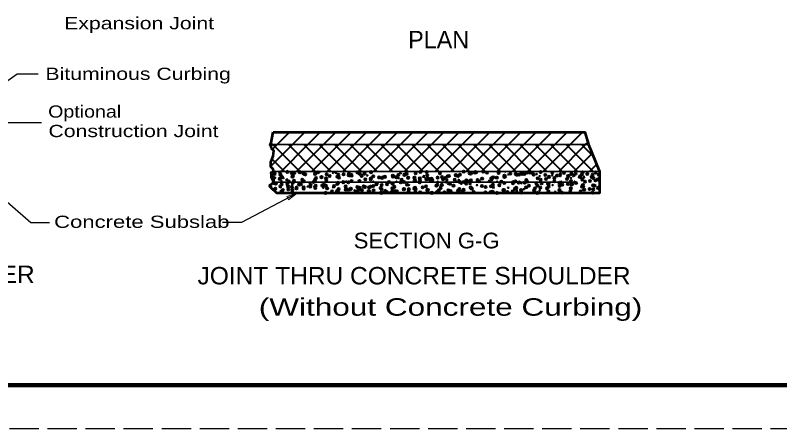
# Model space of a CAD drawing. Extents: x 14 to 49.3, y 28 to 50.
# Drawn here: x 22.75 to 31.51, y 28.04 to 32.78 of the extents above; entities that cross this region are included whole.
import ezdxf

# ---------------------------------------------------------------- set-up
doc = ezdxf.new("R2010")
doc.units = 0
doc.header["$LTSCALE"] = 0.056
doc.header["$PDMODE"] = 32
doc.header["$PDSIZE"] = 0.028
doc.linetypes.add('LONG_DASHED', pattern=[7.5, 6, -1.5])
doc.layers.add('1', color=7, linetype='Continuous', lineweight=35)
doc.layers.add('3', color=7, linetype='Continuous', lineweight=13)

msp = doc.modelspace()

# ---------------------------------------------------------------- hatches: boundary and pattern name
at = {"layer": '3'}
msp.add_hatch(color=256, dxfattribs=at).paths.add_polyline_path([(25.857, 30.706), (25.87625, 30.66908), (25.97725, 30.74567), (25.97725, 30.74567)])

# ---------------------------------------------------------------- linework, layer by layer
at = {"layer": '1', "lineweight": 53}
for p, q in [((25.67508, 31.301), (25.70025, 31.442)), ((29.31292, 31.301), (29.43892, 30.99242)), ((25.6835, 30.97483), (25.73383, 30.99242)), ((25.70767, 30.90667), (25.73192, 30.932)), ((25.70767, 30.86225), (25.70767, 30.90667)), ((25.73192, 30.84317), (25.70767, 30.86225))]:
    msp.add_line(p, q, dxfattribs=at)
at = {"layer": '1', "lineweight": 40}
for p, q in [((25.698, 31.42942), (25.71058, 31.442)), ((25.74633, 31.301), (25.88742, 31.442)), ((25.92317, 31.301), (26.06417, 31.442)), ((26.09992, 31.301), (26.24092, 31.442)), ((26.27667, 31.301), (26.41775, 31.442)), ((26.4535, 31.301), (26.5945, 31.442)), ((26.63025, 31.301), (26.77125, 31.442)), ((26.807, 31.301), (26.94808, 31.442)), ((26.98375, 31.301), (27.12483, 31.442)), ((27.16058, 31.301), (27.30158, 31.442)), ((27.33733, 31.301), (27.47842, 31.442)), ((27.51408, 31.301), (27.65517, 31.442)), ((27.69092, 31.301), (27.83192, 31.442)), ((27.86767, 31.301), (28.00875, 31.442)), ((28.04442, 31.301), (28.1855, 31.442)), ((28.22125, 31.301), (28.36225, 31.442)), ((28.398, 31.301), (28.53908, 31.442)), ((28.57475, 31.301), (28.71583, 31.442)), ((28.75158, 31.301), (28.89258, 31.442)), ((28.92833, 31.301), (29.06942, 31.442)), ((29.10508, 31.301), (29.24617, 31.442)), ((25.67508, 31.05292), (25.92317, 31.301)), ((25.69267, 31.24725), (25.74633, 31.301)), ((26.00733, 30.99242), (25.69883, 31.301)), ((25.79142, 30.99242), (26.09992, 31.301)), ((26.18417, 30.99242), (25.87558, 31.301)), ((25.96817, 30.99242), (26.27667, 31.301)), ((26.36092, 30.99242), (26.05242, 31.301)), ((26.14492, 30.99242), (26.4535, 31.301)), ((26.53767, 30.99242), (26.22917, 31.301)), ((26.32175, 30.99242), (26.63025, 31.301)), ((26.7145, 30.99242), (26.40592, 31.301)), ((26.4985, 30.99242), (26.807, 31.301)), ((26.89125, 30.99242), (26.58275, 31.301)), ((26.67525, 30.99242), (26.98375, 31.301)), ((27.068, 30.99242), (26.7595, 31.301)), ((26.852, 30.99242), (27.16058, 31.301)), ((27.24483, 30.99242), (26.93625, 31.301)), ((27.02883, 30.99242), (27.33733, 31.301)), ((27.42158, 30.99242), (27.11308, 31.301)), ((27.20558, 30.99242), (27.51408, 31.301)), ((27.59833, 30.99242), (27.28983, 31.301)), ((27.38233, 30.99242), (27.69092, 31.301)), ((27.77508, 30.99242), (27.46658, 31.301)), ((27.55917, 30.99242), (27.86767, 31.301)), ((27.95192, 30.99242), (27.64333, 31.301)), ((27.73592, 30.99242), (28.04442, 31.301)), ((28.12867, 30.99242), (27.82017, 31.301)), ((27.91267, 30.99242), (28.22125, 31.301)), ((28.30542, 30.99242), (27.99692, 31.301)), ((28.0895, 30.99242), (28.398, 31.301)), ((28.48225, 30.99242), (28.17367, 31.301)), ((28.26625, 30.99242), (28.57475, 31.301)), ((28.659, 30.99242), (28.3505, 31.301)), ((28.443, 30.99242), (28.75158, 31.301)), ((28.83575, 30.99242), (28.52725, 31.301)), ((28.61983, 30.99242), (28.92833, 31.301)), ((29.01258, 30.99242), (28.704, 31.301)), ((28.79658, 30.99242), (29.10508, 31.301)), ((29.18933, 30.99242), (28.88083, 31.301)), ((28.97333, 30.99242), (29.28192, 31.301)), ((29.36608, 30.99242), (29.05758, 31.301)), ((29.36708, 31.16825), (29.23433, 31.301)), ((29.28192, 31.301), (29.30575, 31.32483)), ((29.15017, 30.99242), (29.35517, 31.1975)), ((25.83058, 30.99242), (25.68817, 31.13483)), ((29.32692, 30.99242), (29.40642, 31.07192))]:
    msp.add_line(p, q, dxfattribs=at)
at = {"layer": '1'}
for p, q in [((25.67508, 31.301), (29.31292, 31.301)), ((25.73383, 30.99242), (29.43892, 30.99242)), ((25.80908, 30.91667), (25.82658, 30.92333)), ((25.82158, 30.90825), (25.82658, 30.92333)), ((26.02633, 30.99242), (26.03158, 30.98892)), ((26.03158, 30.98892), (26.03283, 30.99242)), ((26.23375, 30.99008), (26.23575, 30.99242)), ((26.23375, 30.99008), (26.24867, 30.98875)), ((26.24867, 30.98875), (26.248, 30.99242)), ((26.37842, 30.97725), (26.396, 30.984)), ((26.37842, 30.97725), (26.39092, 30.96883)), ((26.39092, 30.96883), (26.396, 30.984)), ((26.41308, 30.97433), (26.42508, 30.98875)), ((26.41308, 30.97433), (26.428, 30.97308)), ((26.428, 30.97308), (26.42508, 30.98875)), ((26.59233, 30.95867), (26.60442, 30.973)), ((26.59233, 30.95867), (26.60733, 30.95733)), ((26.60733, 30.95733), (26.60442, 30.973)), ((26.73775, 30.95725), (26.75525, 30.96392)), ((26.73775, 30.95725), (26.75017, 30.94883)), ((26.75017, 30.94883), (26.75525, 30.96392)), ((26.77167, 30.943), (26.78375, 30.95733)), ((26.77167, 30.943), (26.78658, 30.94167)), ((26.78667, 30.94167), (26.78375, 30.95733)), ((26.951, 30.92733), (26.96308, 30.94167)), ((26.951, 30.92733), (26.96592, 30.926)), ((26.96592, 30.926), (26.96308, 30.94167)), ((27.097, 30.93725), (27.1145, 30.94392)), ((27.097, 30.93725), (27.10942, 30.92883)), ((27.1095, 30.92883), (27.1145, 30.94392)), ((27.13033, 30.91158), (27.14233, 30.926)), ((27.14525, 30.91033), (27.14233, 30.926)), ((27.14458, 30.96958), (27.164, 30.98983)), ((27.14458, 30.96958), (27.16683, 30.96608)), ((27.16683, 30.96608), (27.164, 30.98983)), ((27.41133, 30.92817), (27.43083, 30.9485)), ((27.41133, 30.92817), (27.43358, 30.92475)), ((27.43358, 30.92475), (27.43083, 30.9485)), ((27.45633, 30.91717), (27.47383, 30.92392)), ((27.45633, 30.91717), (27.46875, 30.90883)), ((27.46875, 30.90883), (27.47383, 30.92392)), ((27.67433, 30.99242), (27.67883, 30.98942)), ((27.67883, 30.98942), (27.67983, 30.99242)), ((28.02567, 30.97783), (28.04317, 30.9845)), ((28.02567, 30.97783), (28.03808, 30.96942)), ((28.03808, 30.96942), (28.04317, 30.9845)), ((28.35083, 30.98983), (28.353, 30.99242)), ((28.35083, 30.98983), (28.36575, 30.9885)), ((28.36575, 30.9885), (28.36508, 30.99242)), ((28.38492, 30.95775), (28.40242, 30.9645)), ((28.38492, 30.95775), (28.39733, 30.94942)), ((28.39733, 30.94942), (28.40242, 30.9645)), ((28.53017, 30.97417), (28.54217, 30.9885)), ((28.53017, 30.97417), (28.54508, 30.97283)), ((28.54508, 30.97283), (28.54217, 30.9885)), ((28.7095, 30.9585), (28.7215, 30.97283)), ((28.7095, 30.9585), (28.72442, 30.95717)), ((28.72442, 30.95717), (28.7215, 30.97283)), ((28.72442, 30.95717), (28.7215, 30.97283)), ((28.74417, 30.93775), (28.76175, 30.9445)), ((28.74417, 30.93775), (28.75667, 30.92933)), ((28.75667, 30.92933), (28.76175, 30.9445)), ((28.88875, 30.94275), (28.90083, 30.95717)), ((28.88875, 30.94275), (28.90375, 30.9415)), ((28.90375, 30.9415), (28.90083, 30.95717)), ((28.97908, 30.96483), (28.99858, 30.98508)), ((28.97908, 30.96483), (29.00133, 30.96133)), ((29.00133, 30.96133), (28.99858, 30.98508)), ((29.06808, 30.92708), (29.08017, 30.94142)), ((29.06808, 30.92708), (29.083, 30.92575)), ((29.083, 30.92575), (29.08017, 30.94142)), ((29.1035, 30.91775), (29.121, 30.92442)), ((29.1035, 30.91775), (29.11592, 30.90933)), ((29.11592, 30.90933), (29.121, 30.92442)), ((29.24592, 30.92342), (29.26533, 30.94375)), ((29.24592, 30.92342), (29.26817, 30.92)), ((29.24742, 30.91142), (29.25942, 30.92575)), ((29.26233, 30.91008), (29.2595, 30.92575)), ((29.26817, 30.92), (29.26542, 30.94375)), ((29.32233, 30.99242), (29.326, 30.99)), ((29.326, 30.99), (29.32683, 30.99242)), ((25.70767, 30.87108), (29.15475, 30.87108)), ((25.7305, 30.84908), (25.7425, 30.86342)), ((25.7305, 30.84908), (25.74542, 30.84775)), ((25.74542, 30.84775), (25.7425, 30.86342)), ((25.80908, 30.91667), (25.82158, 30.90825)), ((25.84367, 30.89158), (25.86317, 30.91183)), ((25.84367, 30.89158), (25.86592, 30.88808)), ((25.86592, 30.88808), (25.86317, 30.91183)), ((25.90983, 30.83342), (25.92183, 30.84775)), ((25.90983, 30.83342), (25.92475, 30.83208)), ((25.92475, 30.83208), (25.92183, 30.84775)), ((26.08908, 30.81767), (26.10117, 30.83208)), ((26.10408, 30.81633), (26.10117, 30.83208)), ((26.1105, 30.85017), (26.12992, 30.8705)), ((26.1105, 30.85017), (26.13267, 30.84675)), ((26.13267, 30.84675), (26.12992, 30.8705)), ((26.16842, 30.89667), (26.18592, 30.90333)), ((26.16842, 30.89667), (26.18083, 30.88825)), ((26.18083, 30.88825), (26.18592, 30.90333)), ((26.52767, 30.87658), (26.54517, 30.88333)), ((26.52767, 30.87658), (26.54008, 30.86825)), ((26.54008, 30.86817), (26.54517, 30.88333)), ((26.887, 30.85658), (26.9045, 30.86333)), ((26.887, 30.85658), (26.89942, 30.84817)), ((26.89942, 30.84817), (26.9045, 30.86333)), ((27.13033, 30.91158), (27.14525, 30.91033)), ((27.24625, 30.83658), (27.26375, 30.84325)), ((27.24625, 30.83658), (27.25867, 30.82817)), ((27.25867, 30.82817), (27.26375, 30.84325)), ((27.30967, 30.89592), (27.32167, 30.91025)), ((27.30967, 30.89592), (27.32458, 30.89458)), ((27.32458, 30.89458), (27.32167, 30.91025)), ((27.48892, 30.88025), (27.501, 30.89458)), ((27.48892, 30.88025), (27.50392, 30.87892)), ((27.50392, 30.87892), (27.501, 30.89458)), ((27.66825, 30.86458), (27.68033, 30.87892)), ((27.66825, 30.86458), (27.68317, 30.86325)), ((27.67817, 30.88683), (27.69767, 30.90708)), ((27.67817, 30.88683), (27.70042, 30.88333)), ((27.68317, 30.86325), (27.68033, 30.87892)), ((27.70042, 30.88333), (27.69767, 30.90708)), ((27.81558, 30.89717), (27.83308, 30.90392)), ((27.81558, 30.89717), (27.828, 30.88875)), ((27.828, 30.88875), (27.83308, 30.90392)), ((27.84758, 30.84883), (27.85958, 30.86325)), ((27.84758, 30.84883), (27.8625, 30.84758)), ((27.8625, 30.8475), (27.85967, 30.86325)), ((27.945, 30.84542), (27.9645, 30.86575)), ((27.945, 30.84542), (27.96725, 30.842)), ((27.96725, 30.842), (27.9645, 30.86575)), ((28.02692, 30.83317), (28.03892, 30.8475)), ((28.02692, 30.83317), (28.04183, 30.83183)), ((28.04183, 30.83183), (28.03892, 30.8475)), ((28.17483, 30.87717), (28.19233, 30.88383)), ((28.17483, 30.87717), (28.18733, 30.86875)), ((28.18733, 30.86875), (28.19233, 30.88383)), ((28.20617, 30.8175), (28.21825, 30.83183)), ((28.22117, 30.81617), (28.21825, 30.83183)), ((28.53417, 30.85717), (28.55167, 30.86383)), ((28.53417, 30.85717), (28.54658, 30.84875)), ((28.54658, 30.84875), (28.55167, 30.86383)), ((28.89342, 30.83708), (28.91092, 30.84383)), ((28.89342, 30.83708), (28.90583, 30.82875)), ((28.90583, 30.82867), (28.91092, 30.84383)), ((29.24742, 30.91142), (29.26233, 30.91008)), ((29.42675, 30.89575), (29.43875, 30.91008)), ((29.42675, 30.89575), (29.43892, 30.89467)), ((29.43892, 30.90942), (29.43875, 30.91008)), ((25.95833, 30.816), (25.97583, 30.82275)), ((25.95833, 30.816), (25.97075, 30.80758)), ((25.97075, 30.80758), (25.97583, 30.82267)), ((26.08908, 30.81767), (26.10408, 30.81642)), ((26.26842, 30.802), (26.2805, 30.81633)), ((26.26842, 30.802), (26.28333, 30.80067)), ((26.28333, 30.80067), (26.2805, 30.81633)), ((26.31767, 30.796), (26.33517, 30.80267)), ((26.31767, 30.796), (26.33008, 30.78758)), ((26.33008, 30.78758), (26.33517, 30.80267)), ((26.37725, 30.80883), (26.39675, 30.82908)), ((26.37725, 30.80883), (26.3995, 30.80533)), ((26.3995, 30.80533), (26.39675, 30.82908)), ((26.44775, 30.78633), (26.45975, 30.80067)), ((26.44775, 30.78633), (26.46267, 30.785)), ((26.46267, 30.785), (26.45983, 30.80067)), ((26.62708, 30.77067), (26.63908, 30.785)), ((26.62708, 30.77067), (26.642, 30.76933)), ((26.642, 30.76933), (26.63908, 30.785)), ((26.64408, 30.76742), (26.66358, 30.78775)), ((26.64408, 30.76742), (26.66633, 30.764)), ((26.66633, 30.764), (26.66358, 30.78775)), ((26.67692, 30.77592), (26.69442, 30.78267)), ((26.67692, 30.77592), (26.68933, 30.76758)), ((26.68933, 30.76758), (26.69442, 30.78267)), ((26.80633, 30.75492), (26.81842, 30.76933)), ((26.80633, 30.75492), (26.82133, 30.75367)), ((26.82133, 30.75358), (26.81842, 30.76933)), ((26.92967, 30.74567), (26.93033, 30.74633)), ((26.93042, 30.74567), (26.93033, 30.74633)), ((26.991, 30.74567), (26.99775, 30.75358)), ((26.99925, 30.74567), (26.99775, 30.75358)), ((27.03617, 30.75592), (27.05367, 30.76267)), ((27.03617, 30.75592), (27.04867, 30.7475)), ((27.04867, 30.7475), (27.05367, 30.76267)), ((27.6055, 30.8165), (27.623, 30.82325)), ((27.6055, 30.8165), (27.618, 30.80817)), ((27.618, 30.80817), (27.623, 30.82325)), ((27.96483, 30.7965), (27.98233, 30.80325)), ((27.96483, 30.7965), (27.97725, 30.78817)), ((27.97725, 30.78808), (27.98233, 30.80325)), ((28.20617, 30.8175), (28.22117, 30.81617)), ((28.21183, 30.80408), (28.23125, 30.82433)), ((28.21183, 30.80408), (28.234, 30.80058)), ((28.234, 30.80058), (28.23125, 30.82433)), ((28.32408, 30.7765), (28.34158, 30.78325)), ((28.32408, 30.7765), (28.3365, 30.76808)), ((28.3365, 30.76808), (28.34158, 30.78317)), ((28.3855, 30.80183), (28.39758, 30.81617)), ((28.3855, 30.80183), (28.4005, 30.8005)), ((28.4005, 30.8005), (28.39758, 30.81617)), ((28.47858, 30.76267), (28.49808, 30.783)), ((28.47858, 30.76267), (28.50083, 30.75925)), ((28.50083, 30.75925), (28.49808, 30.783)), ((28.56483, 30.78608), (28.57692, 30.8005)), ((28.56483, 30.78608), (28.57975, 30.78483)), ((28.57975, 30.78475), (28.57692, 30.8005)), ((28.68342, 30.7565), (28.70092, 30.76317)), ((28.68342, 30.7565), (28.70092, 30.76317)), ((28.68342, 30.7565), (28.69583, 30.74808)), ((28.69583, 30.74808), (28.70092, 30.76317)), ((28.74417, 30.77042), (28.75617, 30.78475)), ((28.74417, 30.77042), (28.75908, 30.76908)), ((28.75908, 30.76908), (28.75617, 30.78475)), ((28.9235, 30.75475), (28.9355, 30.76908)), ((28.9235, 30.75475), (28.93842, 30.75342)), ((28.93842, 30.75342), (28.9355, 30.76908)), ((29.10833, 30.74567), (29.11483, 30.75342)), ((29.11625, 30.74567), (29.11483, 30.75342)), ((29.25275, 30.81708), (29.27025, 30.82383)), ((29.25275, 30.81708), (29.26517, 30.80867)), ((29.26517, 30.80867), (29.27025, 30.82383))]:
    msp.add_line(p, q, dxfattribs=at)
at = {"layer": '1', "linetype": 'LONG_DASHED', "lineweight": 25}
msp.add_line((49.17658, 28.04392), (13.97658, 28.04392), dxfattribs=at)
at = {"layer": '1', "lineweight": 158}
msp.add_lwpolyline([(49.09325, 49.54392), (49.09325, 28.54392), (16.59325, 28.54392)], dxfattribs=at)
at = {"layer": '1', "lineweight": 53}
for points in [[(25.70025, 31.442), (29.27083, 31.442), (29.31292, 31.301)], [(25.70867, 30.98367), (25.70025, 31.01892), (25.67508, 31.04533), (25.67508, 31.09825), (25.70025, 31.16875), (25.70867, 31.23042), (25.6835, 31.25692), (25.67508, 31.301)], [(29.43892, 30.99242), (29.43892, 30.74567), (25.74225, 30.74567), (25.67508, 30.80733), (25.66667, 30.83375), (25.70867, 30.869), (25.6835, 30.92192), (25.6835, 30.97483)]]:
    msp.add_lwpolyline(points, dxfattribs=at)
for start, end in [(0, 180), (180, 0)]:
    msp.add_arc((25.79975, 30.87583), 0.00308, start, end, dxfattribs=at)
at = {"layer": '1', "lineweight": 40}
for centre, radius, start, end in [((26.05275, 30.87583), 0.00308, 0, 180), ((26.05275, 30.87583), 0.00308, 180, 0), ((26.31883, 30.87583), 0.00308, 0, 180), ((26.31883, 30.87583), 0.00308, 180, 0), ((26.56717, 30.87583), 0.00308, 0, 180), ((26.56717, 30.87583), 0.00308, 180, 0), ((26.84767, 30.87583), 0.00308, 0, 180), ((26.84767, 30.87583), 0.00308, 180, 0), ((27.11442, 30.87583), 0.00308, 0, 180), ((27.11442, 30.87583), 0.00308, 180, 0), ((27.33058, 30.87583), 0.00308, 0, 180), ((27.33058, 30.87583), 0.00308, 180, 0), ((27.58758, 30.87583), 0.00304, 0, 180), ((27.58758, 30.87583), 0.00304, 180, 0), ((27.80792, 30.87583), 0.00308, 0, 180), ((27.80792, 30.87583), 0.00308, 180, 0), ((28.05183, 30.87583), 0.00308, 0, 180), ((28.05183, 30.87583), 0.00308, 180, 0), ((28.26733, 30.87583), 0.00304, 0, 180), ((28.26733, 30.87583), 0.00304, 180, 0), ((28.52517, 30.87583), 0.00308, 0, 180), ((28.52517, 30.87583), 0.00308, 180, 0), ((28.75908, 30.87583), 0.00308, 0, 180), ((28.75908, 30.87583), 0.00308, 180, 0), ((29.00258, 30.87583), 0.00304, 0, 180), ((29.00258, 30.87583), 0.00304, 180, 0), ((29.15458, 30.87583), 0.00304, 0, 180), ((29.15458, 30.87583), 0.00304, 180, 0)]:
    msp.add_arc(centre, radius, start, end, dxfattribs=at)
at = {"layer": '1'}
for p in [(25.67508, 31.301), (27.88442, 30.991), (28.10942, 30.99142), (28.1095, 30.99192), (28.6325, 30.99075), (25.6835, 30.97483), (25.69075, 30.94283), (25.71758, 30.963), (25.7775, 30.90808), (25.78017, 30.98208), (25.7855, 30.95525), (25.80117, 30.92858), (25.86342, 30.988), (25.91358, 30.97642), (25.92333, 30.93308), (25.92742, 30.94458), (25.94333, 30.97608), (26.00592, 30.98433), (26.04708, 30.97083), (26.05733, 30.96333), (26.06908, 30.95817), (26.1805, 30.96517), (26.18567, 30.98092), (26.19275, 30.91892), (26.21492, 30.98317), (26.25533, 30.92717), (26.30892, 30.91367), (26.314, 30.9595), (26.35, 30.93967), (26.43875, 30.93242), (26.44742, 30.95392), (26.45617, 30.92067), (26.50792, 30.96042), (26.56708, 30.95008), (26.5705, 30.96867), (26.58092, 30.94825), (26.602, 30.94575), (26.66517, 30.98117), (26.69342, 30.96608), (26.71433, 30.94258), (26.74775, 30.97075), (26.75733, 30.90333), (26.81992, 30.91158), (26.82325, 30.98483), (26.84783, 30.937), (26.91458, 30.924), (26.9485, 30.91917), (26.98125, 30.93133), (27.07242, 30.94483), (27.07483, 30.93517), (27.11475, 30.92567), (27.135, 30.95308), (27.20467, 30.95392), (27.22975, 30.9655), (27.24817, 30.92008), (27.32067, 30.92167), (27.333, 30.9715), (27.38167, 30.91442), (27.38758, 30.98633), (27.45625, 30.90433), (27.45933, 30.9875), (27.46642, 30.94675), (27.47908, 30.90842), (27.51508, 30.90875), (27.58608, 30.92308), (27.61225, 30.97175), (27.637, 30.92917), (27.6485, 30.90317), (27.67217, 30.91683), (27.69958, 30.93742), (27.7145, 30.94067), (27.79425, 30.94992), (27.81792, 30.94183), (27.84075, 30.95667), (27.95217, 30.97067), (27.96375, 30.96692), (27.97058, 30.97542), (28.01475, 30.97892), (28.01792, 30.98533), (28.09592, 30.90975), (28.15133, 30.97975), (28.2015, 30.91358), (28.205, 30.90442), (28.22217, 30.92575), (28.26408, 30.92183), (28.28483, 30.97408), (28.35075, 30.9295), (28.352, 30.9445), (28.35883, 30.93425), (28.41825, 30.96842), (28.48042, 30.96217), (28.49658, 30.9545), (28.51667, 30.95508), (28.55175, 30.96283), (28.57925, 30.96333), (28.60667, 30.97817), (28.64242, 30.9795), (28.674, 30.97575), (28.68517, 30.95717), (28.7335, 30.91367), (28.76592, 30.98508), (28.81867, 30.9515), (28.82867, 30.90617), (28.86183, 30.93125), (28.89942, 30.9795), (28.92333, 30.91867), (28.95208, 30.94592), (28.98808, 30.94725), (29.03283, 30.97383), (29.06942, 30.90542), (29.08125, 30.93942), (29.08558, 30.94025), (29.11792, 30.966), (29.14383, 30.94767), (29.16625, 30.96817), (29.21525, 30.93042), (29.219, 30.93458), (29.2385, 30.96017), (29.24633, 30.98358), (29.29975, 30.96258), (29.35242, 30.929), (29.36108, 30.9555), (29.36958, 30.91642), (29.39642, 30.98092), (29.43317, 30.95692), (25.66975, 30.82775), (25.71967, 30.85667), (25.7315, 30.85433), (25.78417, 30.82075), (25.79817, 30.84533), (25.86492, 30.84867), (25.873, 30.82058), (25.87758, 30.8775), (25.92442, 30.86133), (25.94017, 30.88567), (25.99842, 30.84308), (26.01875, 30.84558), (26.03483, 30.89817), (26.05425, 30.88008), (26.127, 30.82033), (26.13183, 30.83742), (26.16458, 30.87067), (26.18258, 30.89767), (26.18958, 30.82858), (26.26533, 30.83175), (26.28425, 30.84108), (26.30583, 30.8305), (26.31042, 30.89567), (26.39875, 30.82617), (26.43567, 30.84925), (26.44217, 30.86183), (26.50475, 30.87008), (26.53225, 30.8205), (26.56408, 30.86683), (26.59942, 30.88258), (26.69033, 30.88283), (26.73742, 30.82158), (26.81717, 30.81833), (26.82017, 30.90158), (26.84883, 30.82542), (26.88325, 30.84658), (26.9455, 30.83592), (27.00667, 30.84625), (27.029, 30.87167), (27.06925, 30.8545), (27.07175, 30.85192), (27.08892, 30.81675), (27.16392, 30.86692), (27.17483, 30.89667), (27.20158, 30.87067), (27.23475, 30.84175), (27.32183, 30.88775), (27.33, 30.88833), (27.3805, 30.86675), (27.38442, 30.89592), (27.45325, 30.82108), (27.52633, 30.89183), (27.57125, 30.83058), (27.58308, 30.83983), (27.63383, 30.83883), (27.71142, 30.85742), (27.7285, 30.85133), (27.76758, 30.82933), (27.782, 30.8975), (27.83767, 30.87342), (27.88642, 30.87208), (27.91342, 30.85442), (27.91542, 30.89183), (27.949, 30.88033), (27.96758, 30.89217), (28.04367, 30.89283), (28.04892, 30.88625), (28.05917, 30.87942), (28.09283, 30.82658), (28.18233, 30.88058), (28.19833, 30.82325), (28.21917, 30.84258), (28.293, 30.83567), (28.31583, 30.87492), (28.349, 30.86133), (28.44925, 30.86933), (28.45092, 30.8565), (28.47733, 30.87892), (28.5135, 30.86475), (28.58275, 30.86367), (28.60367, 30.89492), (28.60817, 30.87717), (28.63208, 30.83033), (28.71617, 30.858), (28.73042, 30.83042), (28.76608, 30.898), (28.77783, 30.85533), (28.84967, 30.85242), (28.85758, 30.82008), (28.85883, 30.848), (28.92367, 30.88042), (28.98308, 30.84675), (28.98358, 30.8255), (28.98508, 30.86408), (29.0155, 30.84083), (29.07808, 30.84908), (29.11492, 30.88275), (29.11658, 30.84108), (29.12933, 30.8505), (29.17275, 30.86158), (29.24025, 30.81717), (29.24325, 30.90042), (29.25, 30.8355), (29.27517, 30.87558), (29.33058, 30.88233), (29.3665, 30.83317), (29.3835, 30.82983), (29.39325, 30.89058), (29.42092, 30.90058), (25.72717, 30.79558), (25.79508, 30.76208), (25.81183, 30.77883), (25.87442, 30.78708), (25.91767, 30.81508), (25.92133, 30.77808), (25.96908, 30.79958), (26.05108, 30.8095), (26.05125, 30.79683), (26.17958, 30.8145), (26.18458, 30.80383), (26.30008, 30.7465), (26.30283, 30.74725), (26.318, 30.79817), (26.37633, 30.76325), (26.43267, 30.766), (26.43892, 30.7715), (26.44583, 30.7715), (26.4515, 30.79258), (26.53367, 30.78392), (26.561, 30.78358), (26.58492, 30.78692), (26.59167, 30.79658), (26.66567, 30.81483), (26.68733, 30.79958), (26.6915, 30.80475), (26.71842, 30.78125), (26.75408, 30.813), (26.79733, 30.76667), (26.79908, 30.80925), (26.85183, 30.77567), (26.93258, 30.80358), (26.94092, 30.74758), (26.9425, 30.75275), (26.94317, 30.79175), (26.98525, 30.77), (27.0035, 30.75583), (27.066, 30.79792), (27.06875, 30.76875), (27.09817, 30.76833), (27.11875, 30.76433), (27.19858, 30.7875), (27.1995, 30.79233), (27.25217, 30.75875), (27.25608, 30.78908), (27.31867, 30.79733), (27.32692, 30.80508), (27.33025, 30.75425), (27.33292, 30.78667), (27.38567, 30.75308), (27.41333, 30.80983), (27.46642, 30.781), (27.476, 30.77933), (27.51908, 30.74742), (27.58, 30.75658), (27.59983, 30.77542), (27.62183, 30.80433), (27.66275, 30.75267), (27.70842, 30.77417), (27.73333, 30.76975), (27.82058, 30.7735), (27.83467, 30.79025), (27.86675, 30.76408), (27.88317, 30.78175), (27.9645, 30.80892), (27.97792, 30.79417), (28.00025, 30.7585), (28.13367, 30.75283), (28.13575, 30.815), (28.19467, 30.75525), (28.21608, 30.75933), (28.26717, 30.74717), (28.3405, 30.78033), (28.34592, 30.77808), (28.38517, 30.75783), (28.44775, 30.76608), (28.47433, 30.79567), (28.48625, 30.80533), (28.54242, 30.77858), (28.54617, 30.75042), (28.60058, 30.81167), (28.692, 30.77542), (28.70033, 30.79933), (28.72742, 30.74725), (28.76292, 30.80758), (28.83775, 30.8005), (28.85575, 30.76483), (28.982, 30.78083), (29.01225, 30.7505), (29.107, 30.76292), (29.11192, 30.79958), (29.22483, 30.76308), (29.26483, 30.78375), (29.32742, 30.792), (29.3635, 30.74992), (29.37067, 30.78808), (29.42208, 30.80442)]:
    msp.add_point(p, dxfattribs=at)
at = {"layer": '3', "lineweight": 25}
for points in [[(22.53858, 31.95075), (22.76783, 32.11225), (23.00975, 32.11225)], [(22.25983, 31.3255), (22.56683, 31.55275), (23.04583, 31.55275)], [(22.49992, 30.77358), (22.92508, 30.40925), (23.13925, 30.40925)], [(25.97725, 30.74567), (25.33708, 30.40925), (25.11942, 30.40925)]]:
    msp.add_lwpolyline(points, dxfattribs=at)
at = {"layer": '3'}
msp.add_lwpolyline([(25.857, 30.706), (25.87625, 30.66908), (25.97725, 30.74567), (25.97725, 30.74567)], close=True, dxfattribs=at)

# ---------------------------------------------------------------- texts
for s, height, width, p in [('Expansion Joint', 0.14, 1.3, (23.30667, 32.62208)), ('Bituminous Curbing', 0.14, 1.3, (23.09225, 32.04225)), ('Optional', 0.14, 1.2, (23.12325, 31.60967)), ('Construction Joint', 0.14, 1.3, (23.12667, 31.38642)), ('Concrete Subslab', 0.14, 1.35, (23.19192, 30.346)), ('SECTION G-G', 0.18, 1.05, (26.62442, 30.11092)), ('JOINT THRU CONCRETE SHOULDER', 0.2, 1.05, (18.00775, 29.71358)), ('JOINT THRU CONCRETE SHOULDER', 0.2, 1.05, (24.83517, 29.698)), ('(Without Concrete Curbing)', 0.2, 1.35, (25.53667, 29.33933))]:
    msp.add_text(s, height=height, dxfattribs=dict(at, width=width)).set_placement(p)
msp.add_text('PLAN', height=0.2, dxfattribs=at).set_placement((27.24825, 32.40408))

doc.saveas('drawing.dxf')
